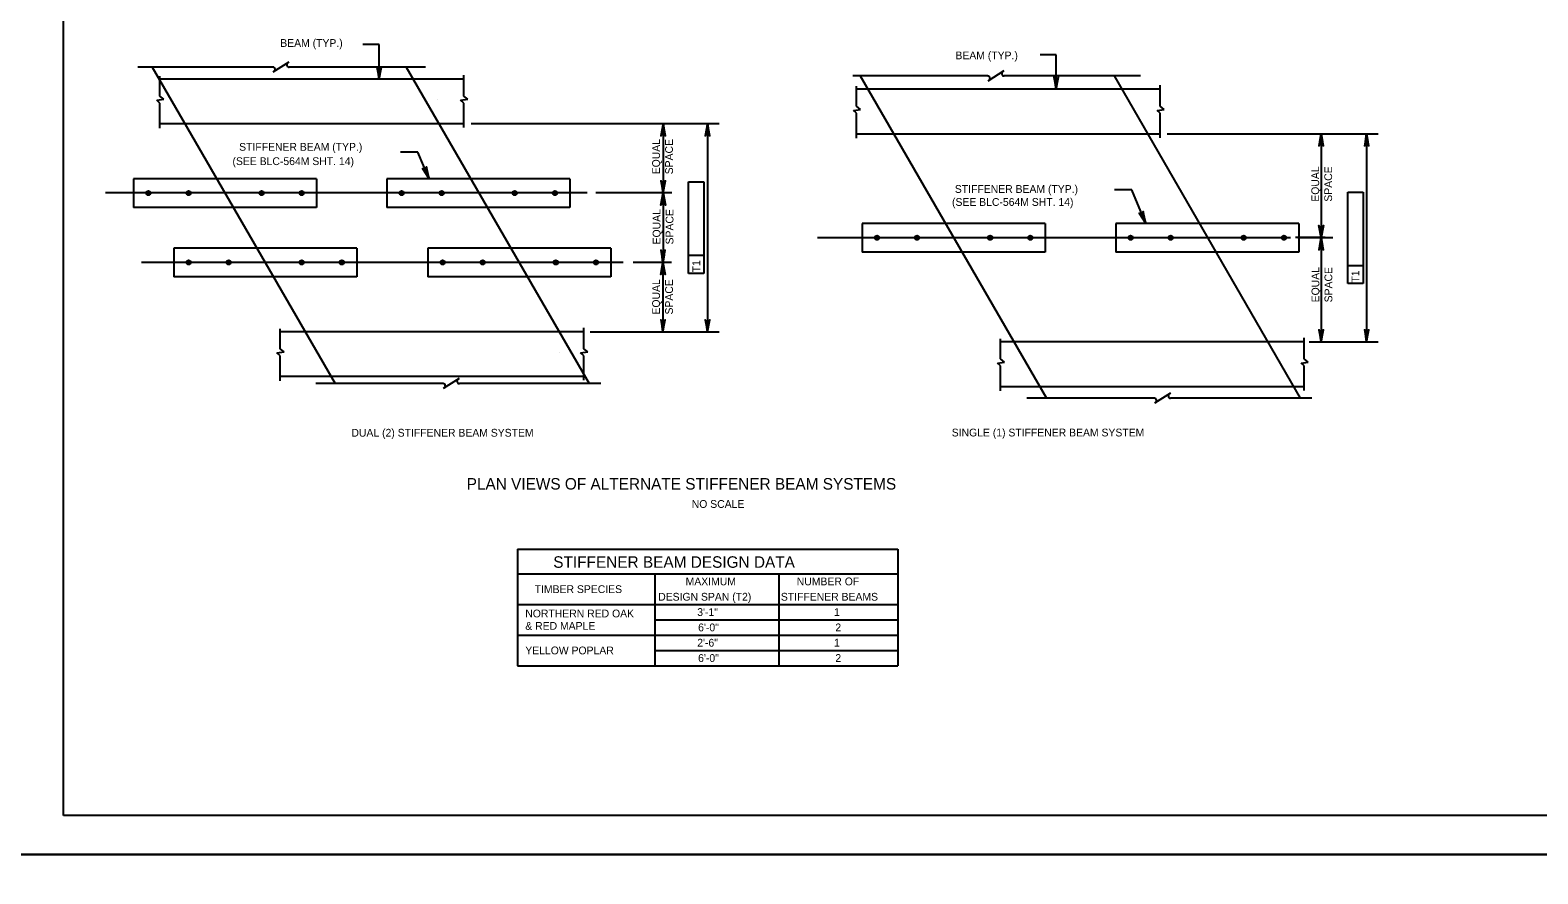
# Model space of a CAD drawing. Extents: x 638175 to 640495, y 294277 to 298435.
# Drawn here: x 639304 to 639885, y 294864 to 295189 of the extents above; entities that cross this region are included whole.
import ezdxf

# ---------------------------------------------------------------- set-up
doc = ezdxf.new("R2010")
doc.units = 0
for name, color, linetype in [('10', 7, 'Continuous'), ('2', 7, 'Continuous'), ('3', 7, 'Continuous'), ('4', 7, 'Continuous'), ('8', 7, 'Continuous'), ('PLT-BNDY', 7, 'Continuous')]:
    doc.layers.add(name, color=color, linetype=linetype)

msp = doc.modelspace()

# ---------------------------------------------------------------- linework, layer by layer
at = {"layer": '10'}
for p, q in [((639491.37, 294989.12), (639491.37, 294944.15)), ((639491.37, 294989.12), (639638.02, 294989.12)), ((639638.02, 294989.12), (639638.02, 294944.15)), ((639491.37, 294979.58), (639638.02, 294979.58)), ((639544.35, 294979.58), (639544.35, 294944.15)), ((639592.12, 294979.58), (639592.12, 294944.15)), ((639491.37, 294967.77), (639638.02, 294967.77)), ((639544.35, 294961.87), (639638.02, 294961.87)), ((639491.37, 294955.96), (639638.02, 294955.96)), ((639544.35, 294950.06), (639638.02, 294950.06)), ((639491.37, 294944.15), (639638.02, 294944.15))]:
    msp.add_line(p, q, dxfattribs=at)
at = {"layer": '2'}
for p, q in [((639316.46, 294886.46), (639316.46, 295450.46)), ((639350.66, 295174.87), (639421.15, 295052.92)), ((639448.49, 295174.87), (639518.98, 295052.92)), ((639623.5, 295171.46), (639695.29, 295047.27)), ((639721.34, 295171.46), (639793.12, 295047.27)), ((640102.46, 294886.46), (639316.46, 294886.46))]:
    msp.add_line(p, q, dxfattribs=at)
at = {"layer": '3'}
for p, q in [((639397.16, 295174.87), (639345.09, 295174.87)), ((639353.61, 295163.71), (639353.61, 295171.43)), ((639403.31, 295176.81), (639397.15, 295172.94)), ((639455.91, 295174.87), (639403.38, 295174.87)), ((639470.69, 295163.71), (639470.69, 295171.81)), ((639672.71, 295171.46), (639620.63, 295171.46)), ((639678.85, 295173.4), (639672.69, 295169.52)), ((639731.46, 295171.46), (639678.92, 295171.46)), ((639470.69, 295170.24), (639353.61, 295170.24)), ((639622.07, 295159.79), (639622.07, 295167.51)), ((639739.15, 295166.32), (639622.07, 295166.32)), ((639739.15, 295159.79), (639739.15, 295167.88)), ((639352.39, 295162.1), (639355.15, 295162.52)), ((639353.61, 295161), (639352.39, 295162.1)), ((639355.15, 295162.52), (639353.61, 295163.71)), ((639353.61, 295151.39), (639353.61, 295161)), ((639469.47, 295162.1), (639472.23, 295162.52)), ((639470.69, 295161), (639469.47, 295162.1)), ((639472.23, 295162.52), (639470.69, 295163.71)), ((639470.69, 295151.58), (639470.69, 295161)), ((639623.62, 295158.6), (639622.07, 295159.79)), ((639740.69, 295158.6), (639739.15, 295159.79)), ((639620.86, 295158.17), (639623.62, 295158.6)), ((639622.07, 295157.08), (639620.86, 295158.17)), ((639622.07, 295147.47), (639622.07, 295157.08)), ((639737.93, 295158.17), (639740.69, 295158.6)), ((639739.15, 295157.08), (639737.93, 295158.17)), ((639739.15, 295147.66), (639739.15, 295157.08)), ((639353.61, 295153.12), (639470.69, 295153.12)), ((639622.07, 295149.2), (639739.15, 295149.2)), ((639413.98, 295131.85), (639343.41, 295131.85)), ((639343.41, 295131.85), (639343.41, 295120.83)), ((639413.98, 295131.85), (639413.98, 295120.83)), ((639511.57, 295131.85), (639441, 295131.85)), ((639441, 295131.85), (639441, 295120.83)), ((639511.57, 295131.85), (639511.57, 295120.83)), ((639476.37, 295126.37), (639476.37, 295126.37)), ((639413.98, 295120.83), (639343.41, 295120.83)), ((639511.57, 295120.83), (639441, 295120.83)), ((639694.8, 295114.65), (639624.22, 295114.65)), ((639624.22, 295114.65), (639624.22, 295103.62)), ((639694.8, 295114.65), (639694.8, 295103.62)), ((639721.97, 295114.65), (639721.97, 295103.62)), ((639792.54, 295114.65), (639721.97, 295114.65)), ((639792.54, 295114.65), (639792.54, 295103.62)), ((639429.46, 295105.1), (639358.89, 295105.1)), ((639358.89, 295105.1), (639358.89, 295094.07)), ((639429.46, 295105.1), (639429.46, 295094.07)), ((639456.81, 295105.1), (639456.81, 295094.07)), ((639527.38, 295105.1), (639456.81, 295105.1)), ((639527.38, 295105.1), (639527.38, 295094.07)), ((639694.8, 295103.62), (639624.22, 295103.62)), ((639792.54, 295103.62), (639721.97, 295103.62)), ((639492.18, 295099.62), (639492.18, 295099.62)), ((639429.46, 295094.07), (639358.89, 295094.07)), ((639527.38, 295094.07), (639456.81, 295094.07)), ((639399.88, 295066.33), (639399.88, 295074.05)), ((639516.96, 295072.86), (639399.88, 295072.86)), ((639516.96, 295066.33), (639516.96, 295074.43)), ((639677.58, 295062.41), (639677.58, 295070.13)), ((639794.66, 295068.94), (639677.58, 295068.94)), ((639794.66, 295062.41), (639794.66, 295070.51)), ((639398.66, 295064.71), (639401.42, 295065.14)), ((639399.88, 295063.62), (639398.66, 295064.71)), ((639401.42, 295065.14), (639399.88, 295066.33)), ((639399.88, 295054.01), (639399.88, 295063.62)), ((639515.74, 295064.71), (639518.49, 295065.14)), ((639516.96, 295063.62), (639515.74, 295064.71)), ((639518.49, 295065.14), (639516.96, 295066.33)), ((639516.96, 295054.2), (639516.96, 295063.62)), ((639676.37, 295060.79), (639679.12, 295061.22)), ((639679.12, 295061.22), (639677.58, 295062.41)), ((639793.44, 295060.79), (639796.2, 295061.22)), ((639796.2, 295061.22), (639794.66, 295062.41)), ((639399.88, 295055.74), (639516.96, 295055.74)), ((639677.58, 295059.7), (639676.37, 295060.79)), ((639677.58, 295050.09), (639677.58, 295059.7)), ((639794.66, 295059.7), (639793.44, 295060.79)), ((639794.66, 295050.28), (639794.66, 295059.7)), ((639462.78, 295052.92), (639413.63, 295052.92)), ((639468.92, 295054.86), (639462.77, 295050.99)), ((639523.48, 295052.92), (639468.99, 295052.92)), ((639677.58, 295051.82), (639794.66, 295051.82)), ((639736.92, 295047.27), (639687.77, 295047.27)), ((639743.06, 295049.21), (639736.9, 295045.34)), ((639797.62, 295047.27), (639743.13, 295047.27))]:
    msp.add_line(p, q, dxfattribs=at)
for centre, radius in [((639349.17, 295126.34), 0.833), ((639349.17, 295126.34), 0.738), ((639349.17, 295126.34), 0.625), ((639349.17, 295126.34), 0.417), ((639349.17, 295126.34), 0.208), ((639364.62, 295126.34), 0.833), ((639364.62, 295126.34), 0.738), ((639364.62, 295126.34), 0.625), ((639364.62, 295126.34), 0.417), ((639364.62, 295126.34), 0.208), ((639392.77, 295126.34), 0.833), ((639392.77, 295126.34), 0.738), ((639392.77, 295126.34), 0.625), ((639392.77, 295126.34), 0.417), ((639392.77, 295126.34), 0.208), ((639408.22, 295126.34), 0.833), ((639408.22, 295126.34), 0.738), ((639408.22, 295126.34), 0.625), ((639408.22, 295126.34), 0.417), ((639408.22, 295126.34), 0.208), ((639446.75, 295126.34), 0.833), ((639446.75, 295126.34), 0.738), ((639446.75, 295126.34), 0.625), ((639446.75, 295126.34), 0.417), ((639446.75, 295126.34), 0.208), ((639462.21, 295126.34), 0.833), ((639462.21, 295126.34), 0.738), ((639462.21, 295126.34), 0.625), ((639462.21, 295126.34), 0.417), ((639462.21, 295126.34), 0.208), ((639490.36, 295126.34), 0.833), ((639490.36, 295126.34), 0.738), ((639490.36, 295126.34), 0.625), ((639490.36, 295126.34), 0.417), ((639490.36, 295126.34), 0.208), ((639505.81, 295126.34), 0.833), ((639505.81, 295126.34), 0.738), ((639505.81, 295126.34), 0.625), ((639505.81, 295126.34), 0.417), ((639505.81, 295126.34), 0.208), ((639629.98, 295109.14), 0.833), ((639629.98, 295109.14), 0.738), ((639629.98, 295109.14), 0.625), ((639629.98, 295109.14), 0.417), ((639629.98, 295109.14), 0.208), ((639645.43, 295109.14), 0.833), ((639645.43, 295109.14), 0.738), ((639645.43, 295109.14), 0.625), ((639645.43, 295109.14), 0.417), ((639645.43, 295109.14), 0.208), ((639673.58, 295109.14), 0.833), ((639673.58, 295109.14), 0.738), ((639673.58, 295109.14), 0.625), ((639673.58, 295109.14), 0.417), ((639673.58, 295109.14), 0.208), ((639689.04, 295109.14), 0.833), ((639689.04, 295109.14), 0.738), ((639689.04, 295109.14), 0.625), ((639689.04, 295109.14), 0.417), ((639689.04, 295109.14), 0.208), ((639727.73, 295109.14), 0.833), ((639727.73, 295109.14), 0.738), ((639727.73, 295109.14), 0.625), ((639727.73, 295109.14), 0.417), ((639727.73, 295109.14), 0.208), ((639743.18, 295109.14), 0.833), ((639743.18, 295109.14), 0.738), ((639743.18, 295109.14), 0.625), ((639743.18, 295109.14), 0.417), ((639743.18, 295109.14), 0.208), ((639771.33, 295109.14), 0.833), ((639771.33, 295109.14), 0.738), ((639771.33, 295109.14), 0.625), ((639771.33, 295109.14), 0.417), ((639771.33, 295109.14), 0.208), ((639786.79, 295109.14), 0.833), ((639786.79, 295109.14), 0.738), ((639786.79, 295109.14), 0.625), ((639786.79, 295109.14), 0.417), ((639786.79, 295109.14), 0.208), ((639364.65, 295099.59), 0.833), ((639364.65, 295099.59), 0.738), ((639364.65, 295099.59), 0.625), ((639364.65, 295099.59), 0.417), ((639364.65, 295099.59), 0.208), ((639380.1, 295099.59), 0.833), ((639380.1, 295099.59), 0.738), ((639380.1, 295099.59), 0.625), ((639380.1, 295099.59), 0.417), ((639380.1, 295099.59), 0.208), ((639408.25, 295099.59), 0.833), ((639408.25, 295099.59), 0.738), ((639408.25, 295099.59), 0.625), ((639408.25, 295099.59), 0.417), ((639408.25, 295099.59), 0.208), ((639423.7, 295099.59), 0.833), ((639423.7, 295099.59), 0.738), ((639423.7, 295099.59), 0.625), ((639423.7, 295099.59), 0.417), ((639423.7, 295099.59), 0.208), ((639462.56, 295099.59), 0.833), ((639462.56, 295099.59), 0.738), ((639462.56, 295099.59), 0.625), ((639462.56, 295099.59), 0.417), ((639462.56, 295099.59), 0.208), ((639478.02, 295099.59), 0.833), ((639478.02, 295099.59), 0.738), ((639478.02, 295099.59), 0.625), ((639478.02, 295099.59), 0.417), ((639478.02, 295099.59), 0.208), ((639506.17, 295099.59), 0.833), ((639506.17, 295099.59), 0.738), ((639506.17, 295099.59), 0.625), ((639506.17, 295099.59), 0.417), ((639506.17, 295099.59), 0.208), ((639521.62, 295099.59), 0.833), ((639521.62, 295099.59), 0.738), ((639521.62, 295099.59), 0.625), ((639521.62, 295099.59), 0.417), ((639521.62, 295099.59), 0.208)]:
    msp.add_circle(centre, radius, dxfattribs=at)
for centre, start, end in [((639397.08, 295173.97), 302.13276, 84.67141), ((639403.38, 295175.78), 120, 270), ((639672.62, 295170.55), 302.13276, 84.67141), ((639678.92, 295172.37), 120, 270), ((639462.69, 295052.02), 302.13276, 84.67141), ((639468.99, 295053.83), 120, 270), ((639736.83, 295046.37), 302.13276, 84.67141), ((639743.13, 295048.18), 120, 270)]:
    msp.add_arc(centre, 0.909, start, end, dxfattribs=at)
at = {"layer": '4'}
for p, q in [((639438.1, 295183.58), (639431.85, 295183.58)), ((639699.05, 295179.66), (639692.83, 295179.66)), ((639473.5, 295153.12), (639558.68, 295153.12)), ((639530.88, 295153.12), (639569.12, 295153.12)), ((639534.7, 295153.12), (639549.76, 295153.12)), ((639547.54, 295153.12), (639547.54, 295126.37)), ((639564.62, 295153.12), (639564.62, 295072.86)), ((639741.74, 295149.2), (639805.67, 295149.2)), ((639792.18, 295149.2), (639823.18, 295149.2)), ((639801.17, 295149.2), (639801.17, 295109.17)), ((639818.68, 295149.2), (639818.68, 295068.94)), ((639453.02, 295142.16), (639446.35, 295142.16)), ((639518.22, 295126.37), (639332.57, 295126.37)), ((639550.91, 295126.37), (639521.54, 295126.37)), ((639547.54, 295126.37), (639547.54, 295102.57)), ((639557.33, 295130.66), (639563.24, 295130.66)), ((639557.33, 295102.83), (639557.33, 295130.66)), ((639563.24, 295130.66), (639563.24, 295095.36)), ((639728.16, 295127.62), (639721.46, 295127.62)), ((639811.39, 295126.74), (639817.29, 295126.74)), ((639811.39, 295098.91), (639811.39, 295126.74)), ((639817.29, 295126.74), (639817.29, 295091.44)), ((639789.34, 295109.14), (639607.06, 295109.14)), ((639802.67, 295109.17), (639791.3, 295109.17)), ((639792.18, 295109.17), (639805.67, 295109.17)), ((639801.17, 295109.17), (639801.17, 295068.94)), ((639557.33, 295095.36), (639557.33, 295102.83)), ((639563.24, 295102.25), (639557.33, 295102.25)), ((639532.08, 295099.58), (639346.43, 295099.58)), ((639550.72, 295099.62), (639536.04, 295099.62)), ((639547.48, 295096.66), (639547.48, 295072.86)), ((639811.39, 295091.44), (639811.39, 295098.91)), ((639817.29, 295098.33), (639811.39, 295098.33)), ((639563.24, 295095.36), (639557.33, 295095.36)), ((639817.29, 295091.44), (639811.39, 295091.44)), ((639519.42, 295072.86), (639569.12, 295072.86)), ((639540.99, 295072.86), (639549.37, 295072.86)), ((639796.48, 295068.94), (639823.18, 295068.94))]:
    msp.add_line(p, q, dxfattribs=at)
for points in [[(639438.1, 295170.24), (639438.1, 295183.58)], [(639699.05, 295166.32), (639699.05, 295179.66)], [(639438.1, 295170.24), (639438.97, 295174.9), (639438.73, 295174.55), (639438.41, 295174.36), (639438.1, 295174.31), (639437.79, 295174.36), (639437.48, 295174.55), (639437.23, 295174.9), (639438.1, 295170.24), (639437.48, 295174.55), (639437.79, 295174.36), (639438.1, 295170.24), (639438.1, 295174.31), (639438.41, 295174.36), (639438.1, 295170.24), (639438.73, 295174.55)], [(639699.05, 295166.32), (639699.92, 295170.98), (639699.67, 295170.62), (639699.36, 295170.44), (639699.05, 295170.38), (639698.74, 295170.44), (639698.42, 295170.62), (639698.18, 295170.98), (639699.05, 295166.32), (639698.42, 295170.62), (639698.74, 295170.44), (639699.05, 295166.32), (639699.05, 295170.38), (639699.36, 295170.44), (639699.05, 295166.32), (639699.67, 295170.62)], [(639547.54, 295153.12), (639546.67, 295148.46), (639546.92, 295148.82), (639547.23, 295149), (639547.54, 295149.06), (639547.85, 295149), (639548.17, 295148.82), (639548.41, 295148.46), (639547.54, 295153.12), (639548.17, 295148.82), (639547.85, 295149), (639547.54, 295153.12), (639547.54, 295149.06), (639547.23, 295149), (639547.54, 295153.12), (639546.92, 295148.82)], [(639564.62, 295153.12), (639563.75, 295148.46), (639563.99, 295148.82), (639564.31, 295149), (639564.62, 295149.06), (639564.93, 295149), (639565.24, 295148.82), (639565.49, 295148.46), (639564.62, 295153.12), (639565.24, 295148.82), (639564.93, 295149), (639564.62, 295153.12), (639564.62, 295149.06), (639564.31, 295149), (639564.62, 295153.12), (639563.99, 295148.82)], [(639801.17, 295149.2), (639800.3, 295144.54), (639800.54, 295144.9), (639800.86, 295145.08), (639801.17, 295145.14), (639801.48, 295145.08), (639801.79, 295144.9), (639802.04, 295144.54), (639801.17, 295149.2), (639801.79, 295144.9), (639801.48, 295145.08), (639801.17, 295149.2), (639801.17, 295145.14), (639800.86, 295145.08), (639801.17, 295149.2), (639800.54, 295144.9)], [(639818.68, 295149.2), (639817.8, 295144.54), (639818.05, 295144.9), (639818.36, 295145.08), (639818.68, 295145.14), (639818.99, 295145.08), (639819.3, 295144.9), (639819.55, 295144.54), (639818.68, 295149.2), (639819.3, 295144.9), (639818.99, 295145.08), (639818.68, 295149.2), (639818.68, 295145.14), (639818.36, 295145.08), (639818.68, 295149.2), (639818.05, 295144.9)], [(639457.33, 295131.85), (639453.02, 295142.16)], [(639457.33, 295131.85), (639456.34, 295136.48), (639456.25, 295136.06), (639456.03, 295135.77), (639455.76, 295135.6), (639455.45, 295135.53), (639455.09, 295135.58), (639454.73, 295135.81), (639457.33, 295131.85), (639455.09, 295135.58), (639455.45, 295135.53), (639457.33, 295131.85), (639455.76, 295135.6), (639456.03, 295135.77), (639457.33, 295131.85), (639456.25, 295136.06)], [(639547.54, 295126.37), (639548.41, 295131.03), (639548.17, 295130.67), (639547.85, 295130.48), (639547.54, 295130.43), (639547.23, 295130.48), (639546.92, 295130.67), (639546.67, 295131.03), (639547.54, 295126.37), (639546.92, 295130.67), (639547.23, 295130.48), (639547.54, 295126.37), (639547.54, 295130.43), (639547.85, 295130.48), (639547.54, 295126.37), (639548.17, 295130.67)], [(639547.54, 295126.37), (639548.41, 295121.71), (639548.17, 295122.07), (639547.85, 295122.25), (639547.54, 295122.31), (639547.23, 295122.25), (639546.92, 295122.07), (639546.67, 295121.71), (639547.54, 295126.37), (639546.92, 295122.07), (639547.23, 295122.25), (639547.54, 295126.37), (639547.54, 295122.31), (639547.85, 295122.25), (639547.54, 295126.37), (639548.17, 295122.07)], [(639733.59, 295114.65), (639728.16, 295127.62)], [(639733.59, 295114.65), (639732.59, 295119.28), (639732.5, 295118.86), (639732.29, 295118.57), (639732.02, 295118.39), (639731.71, 295118.32), (639731.35, 295118.37), (639730.98, 295118.61), (639733.59, 295114.65), (639731.35, 295118.37), (639731.71, 295118.32), (639733.59, 295114.65), (639732.02, 295118.39), (639732.29, 295118.57), (639733.59, 295114.65), (639732.5, 295118.86)], [(639801.17, 295109.17), (639800.3, 295113.83), (639800.54, 295113.47), (639800.86, 295113.28), (639801.17, 295113.23), (639801.48, 295113.28), (639801.79, 295113.47), (639802.04, 295113.83), (639801.17, 295109.17), (639801.79, 295113.47), (639801.48, 295113.28), (639801.17, 295109.17), (639801.17, 295113.23), (639800.86, 295113.28), (639801.17, 295109.17), (639800.54, 295113.47)], [(639801.17, 295109.17), (639800.3, 295104.51), (639800.54, 295104.86), (639800.86, 295105.05), (639801.17, 295105.1), (639801.48, 295105.05), (639801.79, 295104.86), (639802.04, 295104.51), (639801.17, 295109.17), (639801.79, 295104.86), (639801.48, 295105.05), (639801.17, 295109.17), (639801.17, 295105.1), (639800.86, 295105.05), (639801.17, 295109.17), (639800.54, 295104.86)], [(639547.48, 295099.62), (639548.35, 295104.28), (639548.1, 295103.92), (639547.79, 295103.73), (639547.48, 295103.68), (639547.17, 295103.73), (639546.85, 295103.92), (639546.61, 295104.28), (639547.48, 295099.62), (639546.85, 295103.92), (639547.17, 295103.73), (639547.48, 295099.62), (639547.48, 295103.68), (639547.79, 295103.73), (639547.48, 295099.62), (639548.1, 295103.92)], [(639547.48, 295099.62), (639548.35, 295094.96), (639548.1, 295095.31), (639547.79, 295095.5), (639547.48, 295095.55), (639547.17, 295095.5), (639546.85, 295095.31), (639546.61, 295094.96), (639547.48, 295099.62), (639546.85, 295095.31), (639547.17, 295095.5), (639547.48, 295099.62), (639547.48, 295095.55), (639547.79, 295095.5), (639547.48, 295099.62), (639548.1, 295095.31)], [(639547.48, 295072.86), (639548.35, 295077.52), (639548.1, 295077.17), (639547.79, 295076.98), (639547.48, 295076.93), (639547.17, 295076.98), (639546.85, 295077.17), (639546.61, 295077.52), (639547.48, 295072.86), (639546.85, 295077.17), (639547.17, 295076.98), (639547.48, 295072.86), (639547.48, 295076.93), (639547.79, 295076.98), (639547.48, 295072.86), (639548.1, 295077.17)], [(639564.62, 295072.86), (639565.49, 295077.52), (639565.24, 295077.17), (639564.93, 295076.98), (639564.62, 295076.93), (639564.31, 295076.98), (639563.99, 295077.17), (639563.75, 295077.52), (639564.62, 295072.86), (639563.99, 295077.17), (639564.31, 295076.98), (639564.62, 295072.86), (639564.62, 295076.93), (639564.93, 295076.98), (639564.62, 295072.86), (639565.24, 295077.17)], [(639801.17, 295068.94), (639802.04, 295073.6), (639801.79, 295073.24), (639801.48, 295073.06), (639801.17, 295073.01), (639800.86, 295073.06), (639800.54, 295073.24), (639800.3, 295073.6), (639801.17, 295068.94), (639800.54, 295073.24), (639800.86, 295073.06), (639801.17, 295068.94), (639801.17, 295073.01), (639801.48, 295073.06), (639801.17, 295068.94), (639801.79, 295073.24)], [(639818.68, 295068.94), (639819.55, 295073.6), (639819.3, 295073.24), (639818.99, 295073.06), (639818.68, 295073.01), (639818.36, 295073.06), (639818.05, 295073.24), (639817.8, 295073.6), (639818.68, 295068.94), (639818.05, 295073.24), (639818.36, 295073.06), (639818.68, 295068.94), (639818.68, 295073.01), (639818.99, 295073.06), (639818.68, 295068.94), (639819.3, 295073.24)]]:
    msp.add_lwpolyline(points, dxfattribs=at)
for points in [[(639438.1, 295170.24), (639438.07, 295170.36), (639438.13, 295170.36)], [(639699.05, 295166.32), (639699.02, 295166.44), (639699.08, 295166.44)], [(639801.67, 295146.2), (639800.67, 295146.2), (639801.17, 295149.2)], [(639819.18, 295146.2), (639818.18, 295146.2), (639818.68, 295149.2)], [(639457.33, 295131.85), (639457.26, 295131.95), (639457.32, 295131.97)], [(639733.59, 295114.65), (639733.52, 295114.75), (639733.57, 295114.77)], [(639801.67, 295112.17), (639800.67, 295112.17), (639801.17, 295109.17)], [(639801.67, 295106.17), (639800.67, 295106.17), (639801.17, 295109.17)], [(639548.03, 295102.57), (639547.05, 295102.57), (639547.54, 295099.62)], [(639547.97, 295096.66), (639546.99, 295096.66), (639547.48, 295099.62)], [(639547.97, 295075.82), (639546.99, 295075.82), (639547.48, 295072.86)], [(639565.12, 295075.86), (639564.12, 295075.86), (639564.62, 295072.86)], [(639801.67, 295072.13), (639800.67, 295072.13), (639801.17, 295069.13)], [(639819.18, 295071.94), (639818.18, 295071.94), (639818.68, 295068.94)]]:
    msp.add_lwpolyline(points, close=True, dxfattribs=at)
at = {"layer": '8'}
for p, q in [((639460.39, 295162.38), (639460.39, 295162.38)), ((639460.41, 295162.35), (639460.41, 295162.35)), ((639476.37, 295126.37), (639476.37, 295126.37)), ((639492.18, 295099.62), (639492.18, 295099.62)), ((639507.46, 295064.97), (639507.46, 295064.97))]:
    msp.add_line(p, q, dxfattribs=at)
at = {"layer": 'PLT-BNDY'}
for points in [[(639276.46, 295465.46), (640117.46, 295465.46), (640117.46, 294871.46), (639276.46, 294871.46)], [(639276.46, 294871.46), (640117.46, 294871.46), (640117.46, 294277.46), (639276.46, 294277.46)]]:
    msp.add_lwpolyline(points, close=True, dxfattribs=at)

# ---------------------------------------------------------------- texts
at = {"layer": '4'}
for s, height, p in [('BEAM (TYP.)', 3, (639399.97, 295182.68)), ('BEAM (TYP.)', 3, (639660.19, 295177.9)), ('STIFFENER BEAM (TYP.)', 3, (639384.12, 295142.65)), ('(SEE BLC-564M SHT. 14)', 3, (639381.56, 295137.13)), ('STIFFENER BEAM (TYP.)', 3, (639659.97, 295126.41)), ('(SEE BLC-564M SHT. 14)', 3, (639658.87, 295121.4)), ('DUAL (2) STIFFENER BEAM SYSTEM', 3, (639427.4, 295032.46)), ('SINGLE (1) STIFFENER BEAM SYSTEM', 3, (639658.76, 295032.54)), ('PLAN VIEWS OF ALTERNATE STIFFENER BEAM SYSTEMS', 4.4292, (639471.81, 295012.06)), ('NO SCALE', 3, (639558.56, 295005.01)), ('STIFFENER BEAM DESIGN DATA', 4.4292, (639505.19, 294981.92)), ('TIMBER SPECIES', 3, (639498.04, 294972.18)), ('MAXIMUM', 3, (639556.21, 294975.16)), ('NUMBER OF ', 3, (639599.04, 294975.16)), ('DESIGN SPAN (T2)', 3, (639545.63, 294969.25)), ('STIFFENER BEAMS', 3, (639592.91, 294969.25)), ('NORTHERN RED OAK', 3, (639494.41, 294962.8)), ('3\'-1"', 3, (639560.68, 294963.35)), ('1', 3, (639613.4, 294963.35)), ('& RED MAPLE', 3, (639494.41, 294958.02)), ('6\'-0"', 3, (639561.03, 294957.44)), ('2', 3, (639613.92, 294957.44)), ('YELLOW POPLAR', 3, (639494.41, 294948.56)), ('2\'-6"', 3, (639560.68, 294951.54)), ('1', 3, (639613.4, 294951.54)), ('6\'-0"', 3, (639561.03, 294945.63)), ('2', 3, (639613.92, 294945.63))]:
    msp.add_text(s, height=height, dxfattribs=at).set_placement(p)
for p in [(639561.81, 295095.79), (639815.86, 295091.87)]:
    msp.add_text('T1', height=3, rotation=90, dxfattribs=at).set_placement(p)
at = {"layer": '8'}
for s, p in [('EQUAL ', (639546.31, 295133.57)), ('SPACE', (639551.31, 295133.57)), ('EQUAL ', (639800.36, 295123.02)), ('SPACE', (639805.36, 295123.02)), ('EQUAL ', (639546.5, 295106.55)), ('SPACE', (639551.5, 295106.55)), ('EQUAL ', (639800.44, 295084.22)), ('SPACE', (639805.44, 295084.22)), ('EQUAL ', (639546.31, 295079.53)), ('SPACE', (639551.31, 295079.53))]:
    msp.add_text(s, height=3, rotation=89.9708, dxfattribs=at).set_placement(p)

doc.saveas('drawing.dxf')
